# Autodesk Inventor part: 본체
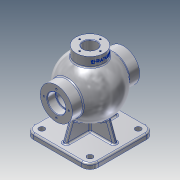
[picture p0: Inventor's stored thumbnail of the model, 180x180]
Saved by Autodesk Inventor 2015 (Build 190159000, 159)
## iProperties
Created: 2025-08
Part Number: 본체
Material: 알루미늄 6061
Document SubType Name: Modeling
Designer: user
Density: 2.7 g/cm^3
Appearance: 알루미늄 - 평지
Mass: 1526.72 g
Surface Area: 1173.82 cm^2
Volume: 565.453 cm^3
Author: user
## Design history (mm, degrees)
sketch "스케치1"
  geometry: L1 (-62.5, -62.5)-(62.5, -62.5); L2 (62.5, -62.5)-(62.5, 62.5); L3 (62.5, 62.5)-(-62.5, 62.5); L4 (-62.5, 62.5)-(-62.5, -62.5); L5 (-62.5, -62.5)-(62.5, 62.5); L6 (62.5, -62.5)-(-62.5, 62.5); 1 further point
  constraints: 12 end point, 2 midpoint, 2 parallel, 1 horizontal, 1 perpendicular
  dimensions: "d0" = 125 distance of L3.end L2.end; "d1" = 125 distance of L2.end L1.end
extrude "돌출1" new body sketch "스케치1" distance "d2" = 10; taper "d3" = 0 deg
fillet "모깎기1" dims "d4" = 16
hole "구멍1" diameter "d7" = 11; stored, may be unused: countersink angle "d11" = 90 deg, drill point angle "d13" = 118 deg; dims "d5" = 16, "d6" = 16, "d8" = 6, "d9" = 4, "d10" = 2, "d12" = 8
sketch "스케치2"
  geometry: L1 (-54, 85)-(54, 85); A1 r 54 centre (0, 85) between (54, 85) and (-54, 85); 2 further points
  constraints: 2 end point, 2 point on circle, 1 centre point, 1 horizontal, 1 midpoint, 1 vertical alignment
  dimensions: "d20" = 108 diameter of A1; "d21" = 85 distance of point (0, 0) A1.centre; "d22" = 108 distance of L1.start L1.end
revolve "회전1" sketch "스케치2" stored, may be unused: angle "d23" = 90 deg
sketch "스케치3"
  geometry: L1 (-44, 85)-(44, 85); C1 r 54 at (0, 85) reference; A1 r 44 centre (0, 85) between (44, 85) and (-44, 85); 1 further point
  constraints: 2 end point, 2 point on circle, 1 centre point, 1 coincident, 1 horizontal
  dimensions: "d24" = 88 diameter of A1; "d25" = 88 distance of L1.start L1.end
revolve "회전2" sketch "스케치3" stored, may be unused: angle "d26" = 90 deg
sketch "스케치4"
  geometry: L1 (-46.5, 62.5)-(46.5, 62.5) reference; L2 (62.5, 46.5)-(62.5, -46.5) reference; L3 (46.5, -62.5)-(-46.5, -62.5) reference; L4 (-62.5, -46.5)-(-62.5, 46.5) reference; L5 (4, 50.5)-(4, -50.5); L6 (4, -50.5)-(-4, -50.5); L7 (-4, -50.5)-(-4, 50.5); L8 (-4, 50.5)-(4, 50.5); L9 (4, 50.5)-(-4, -50.5); L10 (4, -50.5)-(-4, 50.5); L11 (50.5, -4)-(-50.5, -4); L12 (-50.5, -4)-(-50.5, 4); L13 (-50.5, 4)-(50.5, 4); L14 (50.5, 4)-(50.5, -4); L15 (50.5, -4)-(-50.5, 4); L16 (-50.5, -4)-(50.5, 4); C1 r 5.5 at (46.5, 46.5) reference; C2 r 5.5 at (46.5, -46.5) reference; C3 r 5.5 at (-46.5, 46.5) reference; C4 r 5.5 at (-46.5, -46.5) reference; A1 r 16 centre (-46.5, 46.5) between (-46.5, 62.5) and (-62.5, 46.5) reference; A2 r 16 centre (46.5, 46.5) between (62.5, 46.5) and (46.5, 62.5) reference; A3 r 16 centre (46.5, -46.5) between (46.5, -62.5) and (62.5, -46.5) reference; A4 r 16 centre (-46.5, -46.5) between (-62.5, -46.5) and (-46.5, -62.5) reference; 1 further point
  constraints: 24 end point, 4 midpoint, 4 parallel, 2 perpendicular, 1 horizontal, 1 vertical
  dimensions: "d27" = 101 distance of L5.start L5.end; "d28" = 8 distance of L5.end L6.end; "d29" = 101 distance of L11.start L11.end; "d30" = 8 distance of L11.end L12.end
extrude "돌출2" join sketch "스케치4" stored distance "d31" = 10; taper "d32" = 0 deg
feature "면 기울기1" dims angle "d33" = 20 deg
node "작업 평면1"
sketch "스케치5"
  geometry: C1 r 27 at (0, 0); 1 further point
  constraints: 1 centre point, 1 coincident
  dimensions: "d35" = 54 diameter of C1
extrude "돌출3" join sketch "스케치5" stored distance "d36" = 10; taper "d37" = 0 deg
node "작업 평면2"
sketch "스케치6"
  geometry: C1 r 31 at (0, 85); A1 r 54 centre (0, 85) between (37.385, 46.034) and (-37.385, 46.034) reference; 1 further point
  constraints: 1 centre point, 1 coincident
  dimensions: "d39" = 62 diameter of C1
extrude "돌출4" join sketch "스케치6" stored distance "d40" = 10; taper "d41" = 0 deg
hole "구멍2" diameter "d44" = 30; stored, may be unused: countersink angle "d48" = 90 deg, drill point angle "d50" = 0 deg; dims "d42" = 10, "d43" = 10, "d45" = 6, "d46" = 35, "d47" = 16, "d49" = 8
hole "구멍3" diameter "d53" = 26; stored, may be unused: countersink angle "d57" = 90 deg, drill point angle "d59" = 0 deg; dims "d54" = 6, "d55" = 35, "d56" = 16, "d58" = 50, "d60" = 10, "d61" = 10
sketch "스케치7"
  geometry: L1 (0, 0)-(0, 24); C1 r 15 at (0, 0) reference; 1 further point
  constraints: 2 end point, 1 vertical
  dimensions: "d62" = 24 distance of L1.start L1.end
hole "구멍4" sketch "스케치7" at (0, 24) diameter "d63" = 3.242; stored, may be unused: countersink angle "d67" = 90 deg, drill point angle "d69" = 118 deg; dims "d64" = 12, "d65" = 35, "d66" = 16, "d68" = 15
sketch "스케치8"
  geometry: L1 (0, 0)-(20, 0)
  constraints: 2 end point, 1 horizontal
  dimensions: "d73" = 20 distance of L1.start L1.end
hole "구멍5" sketch "스케치8" at (20, 0) diameter "d74" = 3.242; stored, may be unused: countersink angle "d78" = 90 deg, drill point angle "d80" = 118 deg; dims "d75" = 9, "d76" = 35, "d77" = 16, "d79" = 11
chamfer "모따기1" distance "d84" = 1; stored, may be unused: second distance "d85" = 2, angle "d86" = 45 deg
fillet "모깎기2" dims "d87" = 0.6
fillet "모깎기3" dims "d88" = 3
fillet "모깎기4" dims "d89" = 3
fillet "모깎기5" dims "d90" = 3
fillet "모깎기6" dims "d91" = 3
fillet "모깎기7" dims "d92" = 3
sketch "스케치9"
  geometry: L1 (50, 110.621)-(49.026, 109) reference; L2 (49.026, 109)-(50, 107.379) reference; L3 (50, 107.379)-(65, 107.379) reference; L4 (65, 107.379)-(65, 103.5) reference; L5 (65, 103.5)-(64, 102.5) reference; L6 (64, 102.5)-(49.6, 102.5) reference; L7 (49, 101.9)-(49, 100) reference; L8 (49, 100)-(41.364, 100) reference; L9 (13, 127.036)-(13, 149) reference; L10 (13, 149)-(14, 150) reference; L11 (14, 150)-(18.379, 150) reference; L12 (18.379, 150)-(18.379, 139) reference; L13 (18.379, 139)-(20, 138.026) reference; L14 (20, 138.026)-(21.621, 139) reference; L15 (21.621, 139)-(21.621, 150) reference; L16 (21.621, 150)-(27, 150) reference; L17 (27, 150)-(27, 133.466) reference; L18 (45.749, 116)-(65, 116) reference; L19 (65, 116)-(65, 110.621) reference; L20 (65, 110.621)-(50, 110.621) reference; L21 (-50, 59.379)-(-49.026, 61) reference; L22 (-49.026, 61)-(-50, 62.621) reference; L23 (-50, 62.621)-(-65, 62.621) reference; L24 (-65, 62.621)-(-65, 66.5) reference; L25 (-65, 66.5)-(-64, 67.5) reference; L26 (-64, 67.5)-(-49.6, 67.5) reference; L27 (-49, 68.1)-(-49, 70) reference; L28 (-49, 70)-(-41.364, 70) reference; L29 (41.364, 70)-(49, 70) reference; L30 (49, 70)-(49, 68.1) reference; L31 (49.6, 67.5)-(64, 67.5) reference; L32 (64, 67.5)-(65, 66.5) reference; L33 (65, 66.5)-(65, 62.621) reference; L34 (65, 62.621)-(50, 62.621) reference; L35 (50, 62.621)-(49.026, 61) reference; L36 (49.026, 61)-(50, 59.379) reference; L37 (50, 59.379)-(65, 59.379) reference; L38 (65, 59.379)-(65, 54) reference; L39 (65, 54)-(45.749, 54) reference; L40 (38.041, 44.231)-(49.782, 11.974) reference; L41 (52.601, 10)-(59.5, 10) reference; L42 (62.5, 7)-(62.5, 0) reference; L43 (62.5, 0)-(-62.5, 0) reference; L44 (-62.5, 0)-(-62.5, 7) reference; L45 (-59.5, 10)-(-52.601, 10) reference; L46 (-49.782, 11.974)-(-38.041, 44.231) reference; L47 (-45.749, 54)-(-65, 54) reference; L48 (-65, 54)-(-65, 59.379) reference; L49 (-65, 59.379)-(-50, 59.379) reference; L50 (-49.026, 109)-(-50, 110.621) reference; L51 (-50, 110.621)-(-65, 110.621) reference; L52 (-65, 110.621)-(-65, 116) reference; L53 (-65, 116)-(-45.749, 116) reference; L54 (-27, 133.466)-(-27, 150) reference; L55 (-27, 150)-(-21.621, 150) reference; L56 (-21.621, 150)-(-21.621, 139) reference; L57 (-21.621, 139)-(-20, 138.026) reference; L58 (-20, 138.026)-(-18.379, 139) reference; L59 (-18.379, 139)-(-18.379, 150) reference; L60 (-18.379, 150)-(-14, 150) reference; L61 (-14, 150)-(-13, 149) reference; L62 (-13, 149)-(-13, 127.036) reference; L63 (-41.364, 100)-(-49, 100) reference; L64 (-49, 100)-(-49, 101.9) reference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; A1 r 0.6 centre (49.6, 101.9) between (49.6, 102.5) and (49, 101.9) reference; A2 r 44 centre (0, 85) between (41.364, 100) and (13, 127.036) reference; A3 r 3 centre (30, 133.466) between (27, 133.466) and (28.421, 130.916) reference; A4 r 54 centre (0, 85) between (43.341, 117.211) and (28.421, 130.916) reference; A5 r 3 centre (45.749, 119) between (43.341, 117.211) and (45.749, 116) reference; A6 r 0.6 centre (-49.6, 68.1) between (-49.6, 67.5) and (-49, 68.1) reference; A7 r 44 centre (0, 85) between (-41.364, 70) and (41.364, 70) reference; A8 r 0.6 centre (49.6, 68.1) between (49, 68.1) and (49.6, 67.5) reference; A9 r 3 centre (45.749, 51) between (45.749, 54) and (43.341, 52.789) reference; A10 r 54 centre (0, 85) between (38.709, 47.349) and (43.341, 52.789) reference; A11 r 3 centre (40.86, 45.257) between (38.709, 47.349) and (38.041, 44.231) reference; A12 r 3 centre (52.601, 13) between (49.782, 11.974) and (52.601, 10) reference; A13 r 3 centre (59.5, 7) between (62.5, 7) and (59.5, 10) reference; A14 r 3 centre (-59.5, 7) between (-59.5, 10) and (-62.5, 7) reference; A15 r 3 centre (-52.601, 13) between (-52.601, 10) and (-49.782, 11.974) reference; A16 r 3 centre (-40.86, 45.257) between (-38.041, 44.231) and (-38.709, 47.349) reference; A17 r 54 centre (0, 85) between (-43.341, 52.789) and (-38.709, 47.349) reference; A18 r 3 centre (-45.749, 51) between (-43.341, 52.789) and (-45.749, 54) reference; A19 r 3 centre (-45.749, 119) between (-45.749, 116) and (-43.341, 117.211) reference; A20 r 54 centre (0, 85) between (-28.421, 130.916) and (-43.341, 117.211) reference; A21 r 3 centre (-30, 133.466) between (-28.421, 130.916) and (-27, 133.466) reference; A22 r 44 centre (0, 85) between (-13, 127.036) and (-41.364, 100) reference; A23 r 0.6 centre (-49.6, 101.9) between (-49, 101.9) and (-49.6, 102.5) reference; 2 further points
  constraints: 1 vertical alignment, 1 other
  dimensions: "d93" = 9 distance from line of L55 point (0, 141)
feature "엠보싱1" sketch "스케치9" dims "d0" = 125, "d1" = 125, "d94" = 0.5, "d95" = 0
node "솔리드1"
pattern_linear "직사각형 패턴1" dims "d16" = 93, "d19" = 93
mirror "대칭1"
pattern_circular "원형 패턴1" dims angle "d71" = 360 deg
mirror "대칭2"
pattern_circular "원형 패턴2" dims angle "d82" = 360 deg
node "절단 모서리 투영1"
node "절단 모서리 투영2"
other parameters: "d38" = -65
